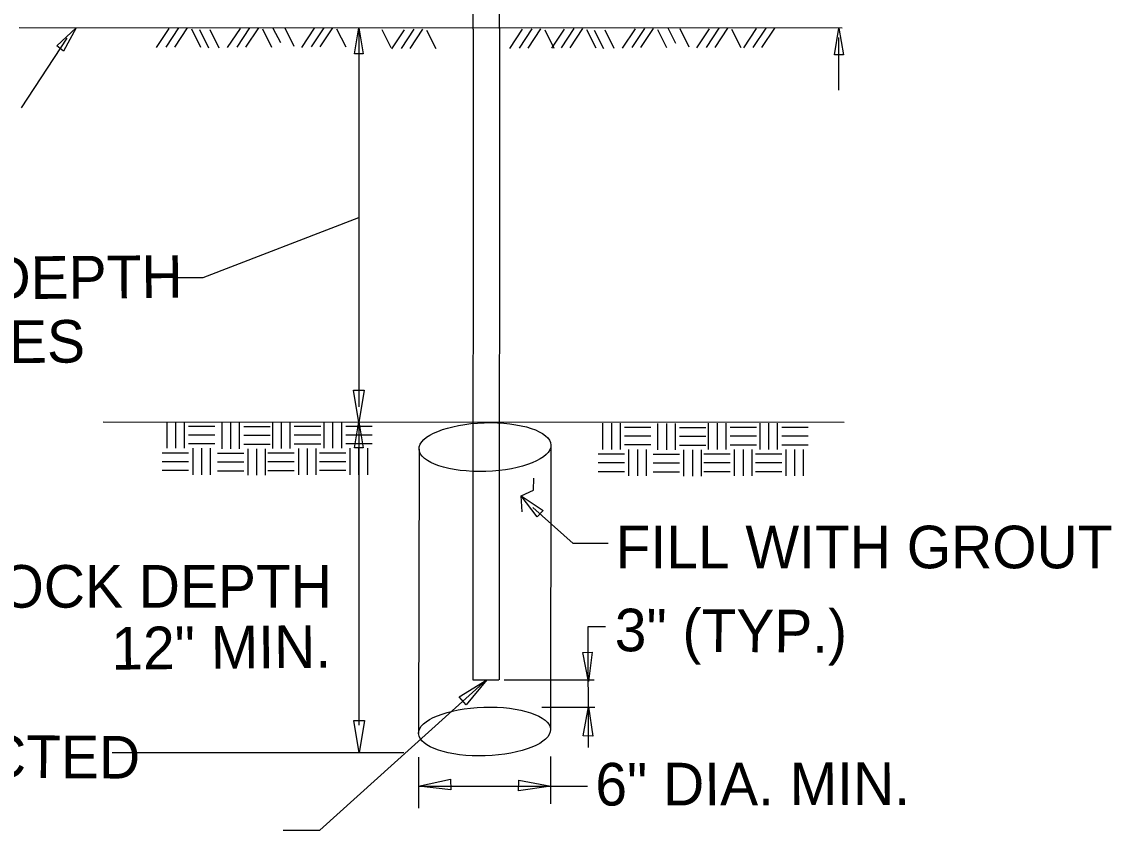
# Model space of a CAD drawing. Extents: x 0 to 2.85, y -0.1 to 1.83.
# Drawn here: x 1.0563 to 1.312, y 0.2411 to 0.4307 of the extents above; entities that cross this region are included whole.
import ezdxf

# ---------------------------------------------------------------- set-up
doc = ezdxf.new("R2010")
doc.units = 0
for name, color, linetype in [('CT_Dimensions', 7, 'Continuous'), ('Grout', 7, 'Continuous'), ('Rock Pattern', 7, 'Continuous'), ('sb_Dimension Lines', 7, 'Continuous'), ('sb_Earth', 7, 'Continuous'), ('sb_Existing Structural Steel', 7, 'Continuous')]:
    doc.layers.add(name, color=color, linetype=linetype)

# ---------------------------------------------------------------- blocks, each defined once
blk = doc.blocks.new('Dimension Terminator')
at = {"layer": 'sb_Dimension Lines'}
blk.add_lwpolyline([(-3.02, 0.5), (0, 0), (-3.02, -0.5)], close=True, dxfattribs=at)

msp = doc.modelspace()

# ---------------------------------------------------------------- linework, layer by layer
at = {"layer": 'CT_Dimensions'}
for p, q in [((1.13538, 0.42919), (1.13538, 0.34038)), ((1.24801, 0.41466), (1.24801, 0.42708)), ((1.05616, 0.41057), (1.06689, 0.42687)), ((1.09885, 0.37073), (1.13538, 0.38479)), ((1.09187, 0.37073), (1.09885, 0.37073)), ((1.13537, 0.33674), (1.13537, 0.26572)), ((1.1764, 0.32087), (1.17647, 0.32369)), ((1.17344, 0.31954), (1.1764, 0.32087)), ((1.17371, 0.31574), (1.17344, 0.31954)), ((1.1857, 0.30831), (1.17621, 0.31675)), ((1.19389, 0.30831), (1.1857, 0.30831)), ((1.18929, 0.2605), (1.18923, 0.28888)), ((1.18923, 0.28888), (1.1933, 0.28888)), ((1.12624, 0.24107), (1.16524, 0.27624)), ((1.19063, 0.27628), (1.16947, 0.27628)), ((1.17835, 0.26996), (1.19077, 0.26996)), ((1.07746, 0.25933), (1.14593, 0.25933)), ((1.18035, 0.25837), (1.18034, 0.24724)), ((1.14939, 0.25818), (1.14938, 0.24626)), ((1.14933, 0.25143), (1.18906, 0.25143)), ((1.1176, 0.24107), (1.12624, 0.24107))]:
    msp.add_line(p, q, dxfattribs=at)
msp.add_lwpolyline([(1.24699, 0.42295), (1.24804, 0.42924), (1.24909, 0.42295)], close=True, dxfattribs=at)
at = {"layer": 'Grout'}
for p, q in [((1.14951, 0.33046), (1.1494, 0.26373)), ((1.18047, 0.33144), (1.18036, 0.26471))]:
    msp.add_line(p, q, dxfattribs=at)
for centre in [(1.16499, 0.33095), (1.16488, 0.26422)]:
    msp.add_ellipse(centre, major_axis=(0.01548, 0.00049), ratio=0.369123, dxfattribs=at)
at = {"layer": 'Rock Pattern'}
for p, q in [((1.24928, 0.33674), (1.07534, 0.33678)), ((1.09028, 0.33684), (1.09028, 0.33066)), ((1.09234, 0.33684), (1.09234, 0.33066)), ((1.0944, 0.33684), (1.0944, 0.33066)), ((1.10161, 0.33581), (1.09543, 0.33581)), ((1.1032, 0.33674), (1.1032, 0.33056)), ((1.10526, 0.33674), (1.10526, 0.33056)), ((1.10732, 0.33674), (1.10732, 0.33056)), ((1.11453, 0.33571), (1.10835, 0.33571)), ((1.11508, 0.33682), (1.11508, 0.33064)), ((1.11714, 0.33682), (1.11714, 0.33064)), ((1.1192, 0.33682), (1.1192, 0.33064)), ((1.12642, 0.33579), (1.12023, 0.33579)), ((1.12715, 0.33684), (1.12715, 0.33066)), ((1.12921, 0.33684), (1.12921, 0.33066)), ((1.13127, 0.33684), (1.13127, 0.33066)), ((1.13849, 0.33581), (1.13231, 0.33581)), ((1.19259, 0.3366), (1.19259, 0.33042)), ((1.19466, 0.3366), (1.19466, 0.33042)), ((1.19672, 0.3366), (1.19672, 0.33042)), ((1.20393, 0.33557), (1.19775, 0.33557)), ((1.20551, 0.3365), (1.20551, 0.33032)), ((1.20757, 0.3365), (1.20757, 0.33032)), ((1.20963, 0.3365), (1.20963, 0.33032)), ((1.21685, 0.33547), (1.21066, 0.33547)), ((1.2174, 0.33658), (1.2174, 0.3304)), ((1.21946, 0.33658), (1.21946, 0.3304)), ((1.22152, 0.33658), (1.22152, 0.3304)), ((1.22873, 0.33555), (1.22255, 0.33555)), ((1.22947, 0.33659), (1.22947, 0.33041)), ((1.23153, 0.33659), (1.23153, 0.33041)), ((1.23359, 0.33659), (1.23359, 0.33041)), ((1.2408, 0.33556), (1.23462, 0.33556)), ((1.10161, 0.33375), (1.09543, 0.33375)), ((1.11453, 0.33365), (1.10835, 0.33365)), ((1.12642, 0.33373), (1.12023, 0.33373)), ((1.13849, 0.33375), (1.13231, 0.33375)), ((1.20393, 0.33351), (1.19775, 0.33351)), ((1.21685, 0.33341), (1.21066, 0.33341)), ((1.22873, 0.33349), (1.22255, 0.33349)), ((1.2408, 0.3335), (1.23462, 0.3335)), ((1.10161, 0.33169), (1.09543, 0.33169)), ((1.09646, 0.32448), (1.09646, 0.33066)), ((1.09852, 0.32448), (1.09852, 0.33066)), ((1.10058, 0.32448), (1.10058, 0.33066)), ((1.11453, 0.33159), (1.10835, 0.33159)), ((1.10938, 0.32438), (1.10938, 0.33056)), ((1.11144, 0.32438), (1.11144, 0.33056)), ((1.1135, 0.32438), (1.1135, 0.33056)), ((1.12642, 0.33167), (1.12023, 0.33167)), ((1.12126, 0.32446), (1.12126, 0.33064)), ((1.12333, 0.32446), (1.12333, 0.33064)), ((1.12539, 0.32446), (1.12539, 0.33064)), ((1.13849, 0.33169), (1.13231, 0.33169)), ((1.13334, 0.32447), (1.13334, 0.33066)), ((1.1354, 0.32447), (1.1354, 0.33066)), ((1.13746, 0.32447), (1.13746, 0.33066)), ((1.20393, 0.33145), (1.19775, 0.33145)), ((1.19878, 0.32423), (1.19878, 0.33042)), ((1.20084, 0.32423), (1.20084, 0.33042)), ((1.2029, 0.32423), (1.2029, 0.33042)), ((1.21685, 0.33135), (1.21066, 0.33135)), ((1.21169, 0.32414), (1.21169, 0.33032)), ((1.21376, 0.32414), (1.21376, 0.33032)), ((1.21582, 0.32414), (1.21582, 0.33032)), ((1.22873, 0.33143), (1.22255, 0.33143)), ((1.22358, 0.32421), (1.22358, 0.3304)), ((1.22564, 0.32421), (1.22564, 0.3304)), ((1.2277, 0.32421), (1.2277, 0.3304)), ((1.2408, 0.33144), (1.23462, 0.33144)), ((1.23565, 0.32423), (1.23565, 0.33041)), ((1.23771, 0.32423), (1.23771, 0.33041)), ((1.23977, 0.32423), (1.23977, 0.33041)), ((1.08925, 0.32963), (1.09543, 0.32963)), ((1.08925, 0.32757), (1.09543, 0.32757)), ((1.10217, 0.32953), (1.10835, 0.32953)), ((1.10217, 0.32747), (1.10835, 0.32747)), ((1.11405, 0.32961), (1.12023, 0.32961)), ((1.11405, 0.32755), (1.12023, 0.32755)), ((1.12612, 0.32963), (1.13231, 0.32963)), ((1.12612, 0.32756), (1.13231, 0.32756)), ((1.19156, 0.32938), (1.19775, 0.32938)), ((1.19156, 0.32732), (1.19775, 0.32732)), ((1.20448, 0.32929), (1.21066, 0.32929)), ((1.21637, 0.32937), (1.22255, 0.32937)), ((1.21637, 0.3273), (1.22255, 0.3273)), ((1.22844, 0.32938), (1.23462, 0.32938)), ((1.22844, 0.32732), (1.23462, 0.32732)), ((1.08925, 0.32551), (1.09543, 0.32551)), ((1.10217, 0.32541), (1.10835, 0.32541)), ((1.11405, 0.32549), (1.12023, 0.32549)), ((1.12612, 0.3255), (1.13231, 0.3255)), ((1.19156, 0.32526), (1.19775, 0.32526)), ((1.20448, 0.32723), (1.21066, 0.32723)), ((1.20448, 0.32517), (1.21066, 0.32517)), ((1.21637, 0.32524), (1.22255, 0.32524)), ((1.22844, 0.32526), (1.23462, 0.32526))]:
    msp.add_line(p, q, dxfattribs=at)
at = {"layer": 'sb_Earth'}
for p, q in [((1.24878, 0.42924), (1.05562, 0.42929)), ((1.09081, 0.42918), (1.08781, 0.42468)), ((1.09306, 0.42929), (1.09006, 0.42479)), ((1.0951, 0.42929), (1.0921, 0.42479)), ((1.09606, 0.42907), (1.0982, 0.42479)), ((1.09794, 0.4289), (1.10008, 0.42461)), ((1.10039, 0.42893), (1.10254, 0.42465)), ((1.1075, 0.42919), (1.1045, 0.42469)), ((1.10975, 0.4293), (1.10675, 0.4248)), ((1.11179, 0.4293), (1.10879, 0.4248)), ((1.11275, 0.42908), (1.11489, 0.4248)), ((1.11522, 0.42924), (1.11698, 0.42587)), ((1.118, 0.4293), (1.12014, 0.42501)), ((1.12492, 0.42922), (1.12192, 0.42472)), ((1.12716, 0.42932), (1.12417, 0.42482)), ((1.1292, 0.42932), (1.1262, 0.42482)), ((1.13016, 0.42911), (1.13231, 0.42482)), ((1.14077, 0.42896), (1.14291, 0.42468)), ((1.14603, 0.42888), (1.14303, 0.42438)), ((1.14827, 0.42899), (1.14528, 0.42449)), ((1.15031, 0.42899), (1.14731, 0.42449)), ((1.15127, 0.42877), (1.15342, 0.42449)), ((1.17374, 0.42898), (1.17074, 0.42448)), ((1.17599, 0.42908), (1.17299, 0.42458)), ((1.17802, 0.42908), (1.17502, 0.42458)), ((1.17899, 0.42887), (1.18113, 0.42458)), ((1.1836, 0.42903), (1.1806, 0.42453)), ((1.18585, 0.42913), (1.18285, 0.42463)), ((1.18788, 0.42913), (1.18488, 0.42463)), ((1.18884, 0.42892), (1.19099, 0.42463)), ((1.19064, 0.42877), (1.19279, 0.42449)), ((1.1931, 0.42881), (1.19524, 0.42452)), ((1.20021, 0.42907), (1.19721, 0.42457)), ((1.20246, 0.42917), (1.19946, 0.42467)), ((1.20449, 0.42917), (1.2015, 0.42467)), ((1.20546, 0.42896), (1.2076, 0.42467)), ((1.20792, 0.42928), (1.20969, 0.42575)), ((1.21071, 0.42917), (1.21285, 0.42489)), ((1.21762, 0.42909), (1.21462, 0.42459)), ((1.21987, 0.4292), (1.21687, 0.4247)), ((1.22191, 0.4292), (1.21891, 0.4247)), ((1.22287, 0.42898), (1.22501, 0.4247)), ((1.22862, 0.42912), (1.22562, 0.42462)), ((1.23087, 0.42923), (1.22787, 0.42473)), ((1.23291, 0.42923), (1.22991, 0.42473))]:
    msp.add_line(p, q, dxfattribs=at)
at = {"layer": 'sb_Existing Structural Steel'}
for p, q in [((1.16218, 0.429), (1.1623, 0.56942)), ((1.16838, 0.42914), (1.1685, 0.56942)), ((1.16218, 0.429), (1.16213, 0.27633)), ((1.16838, 0.42914), (1.16834, 0.27633)), ((1.16215, 0.27631), (1.16825, 0.27631))]:
    msp.add_line(p, q, dxfattribs=at)

# ---------------------------------------------------------------- block references
at = {"layer": 'CT_Dimensions'}
for p, xscale, yscale, rotation in [((1.06901, 0.42931), 0.0020300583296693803, 0.0020300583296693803, 52.45271937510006), ((1.13539, 0.42931), 0.0020300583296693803, 0.0020300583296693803, 90), ((1.17344, 0.31954), 0.00203005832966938, 0.0020300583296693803, 136.85568054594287), ((1.18926, 0.27598), 0.002255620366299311, 0.002255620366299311, -88.15281728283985), ((1.16544, 0.27636), 0.00250624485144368, 0.00250624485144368, 40.918710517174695), ((1.18928, 0.27), 0.002255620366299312, 0.002255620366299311, 88.91083049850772), ((1.13544, 0.25923), 0.0025062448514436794, 0.0025062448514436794, -90), ((1.14936, 0.25143), 0.0025062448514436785, 0.0025062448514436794, -177.3724751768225), ((1.18047, 0.25143), 0.0025062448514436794, 0.0025062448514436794, -0.7264294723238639)]:
    msp.add_blockref('Dimension Terminator', p, dxfattribs=dict(at, xscale=xscale, yscale=yscale, rotation=rotation))
at = {"layer": 'Rock Pattern'}
for p, xscale, yscale, rotation in [((1.13537, 0.33674), 0.0025062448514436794, 0.0025062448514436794, -90), ((1.1354, 0.33687), 0.0020300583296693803, 0.0020300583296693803, 90)]:
    msp.add_blockref('Dimension Terminator', p, dxfattribs=dict(at, xscale=xscale, yscale=yscale, rotation=rotation))

# ---------------------------------------------------------------- texts
at = {"layer": 'CT_Dimensions'}
for s, rotation, p in [('SOIL DEPTH', 0.4595, (1.01454, 0.36535)), ('  VARIES', 0.4595, (1.01466, 0.35035)), ('ROCK DEPTH', 0.0158, (1.04138, 0.29327)), ('3" (TYP.)', 359.6101, (1.19541, 0.28306)), ('12" MIN.', 0.5238, (1.07734, 0.27873)), ('CUT FENCE POST AS DIRECTED', 359.6101, (0.87375, 0.25458)), ('6" DIA. MIN.', 0.1283, (1.1909, 0.24684))]:
    msp.add_text(s, height=0.01, rotation=rotation, dxfattribs=at).set_placement(p)
msp.add_text('FILL WITH GROUT', height=0.01, dxfattribs=at).set_placement((1.19563, 0.30251))

doc.saveas('drawing.dxf')
